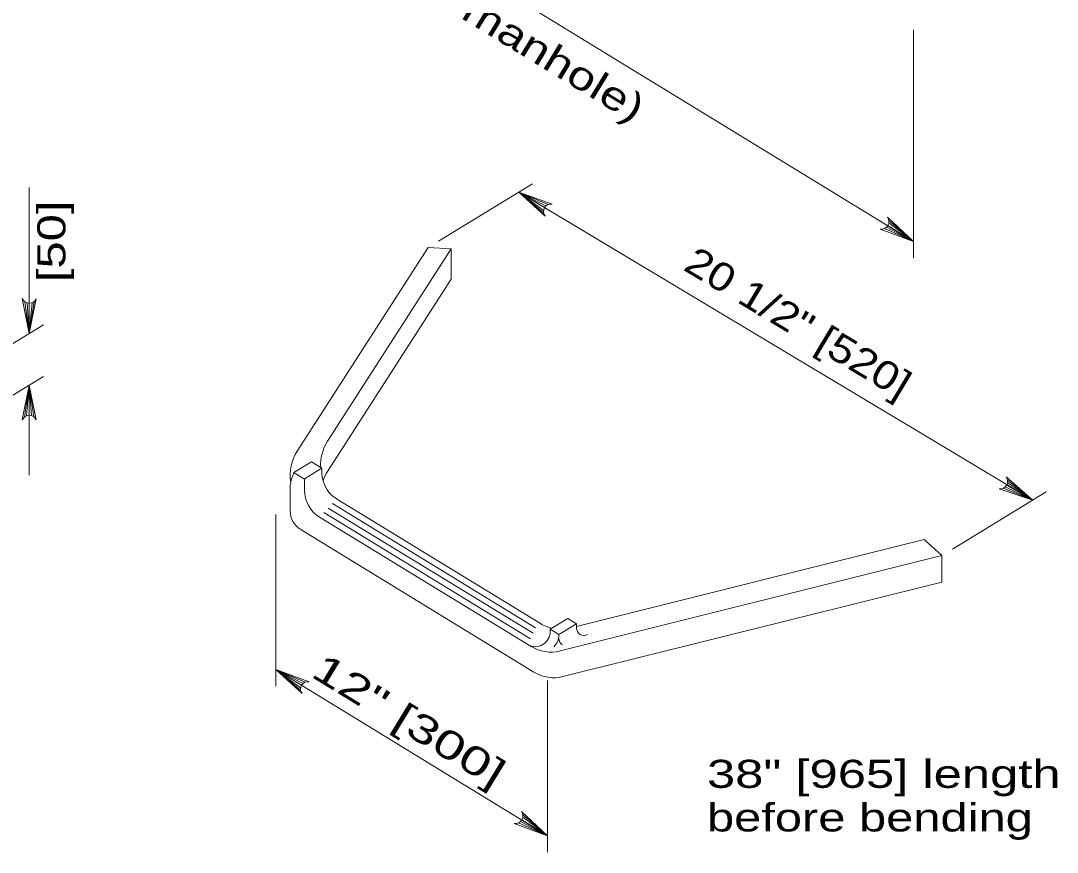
# Model space of a CAD drawing. Extents: x 1083.1 to 1117.1, y 697.4 to 741.4.
# Drawn here: x 1093.86 to 1099.62, y 705.78 to 710.4 of the extents above; entities that cross this region are included whole.
import ezdxf
from ezdxf.enums import TextEntityAlignment as Align

# ---------------------------------------------------------------- set-up
doc = ezdxf.new("R2010")
doc.units = 0
doc.header["$LTSCALE"] = 0.062
doc.layers.add('1', color=7, linetype='Continuous', lineweight=13)

msp = doc.modelspace()

# ---------------------------------------------------------------- linework, layer by layer
at = {"layer": '1'}
for p, q in [((1093.9525, 712.147), (1098.82075, 709.17125)), ((1098.82075, 709.07908), (1098.82075, 710.34608)), ((1093.91117, 709.47075), (1093.91117, 708.66008)), ((1096.1835, 709.17208), (1096.7045, 709.4905)), ((1096.77233, 709.35842), (1096.62867, 709.44417)), ((1096.76692, 709.34333), (1096.62867, 709.44417)), ((1096.76683, 709.33017), (1096.62867, 709.44417)), ((1096.78017, 709.36808), (1096.62867, 709.44417)), ((1096.7915, 709.3755), (1096.62867, 709.44417)), ((1096.62867, 709.44417), (1099.4825, 707.73375)), ((1098.684, 709.287), (1098.82075, 709.17125)), ((1098.65883, 709.242), (1098.82075, 709.17125)), ((1098.67017, 709.24925), (1098.82075, 709.17125)), ((1098.67825, 709.25883), (1098.82075, 709.17125)), ((1098.68383, 709.27383), (1098.82075, 709.17125)), ((1095.39808, 708.006), (1096.12508, 709.13633)), ((1095.56725, 708.06217), (1096.254, 709.12983)), ((1096.12508, 709.13633), (1096.254, 709.12983)), ((1096.254, 708.9615), (1096.254, 709.12983)), ((1095.56683, 707.89325), (1096.254, 708.9615)), ((1093.88667, 708.83508), (1093.91117, 708.66008)), ((1093.89875, 708.82917), (1093.91117, 708.66008)), ((1093.93817, 708.83717), (1093.91117, 708.66008)), ((1093.92683, 708.83042), (1093.91117, 708.66008)), ((1093.91117, 708.82733), (1093.91117, 708.66008)), ((1093.30033, 708.28675), (1093.98983, 708.70817)), ((1093.30033, 707.99925), (1093.98983, 708.42067)), ((1093.88408, 708.1955), (1093.91117, 708.37258)), ((1093.89542, 708.20225), (1093.91117, 708.37258)), ((1093.91117, 708.20533), (1093.91117, 708.37258)), ((1093.9235, 708.2035), (1093.91117, 708.37258)), ((1093.93558, 708.19758), (1093.91117, 708.37258)), ((1093.91117, 708.37258), (1093.91117, 707.872)), ((1095.37983, 707.88767), (1095.47742, 707.94733)), ((1095.43875, 707.85167), (1095.53633, 707.91133)), ((1095.53633, 707.91133), (1095.47742, 707.94733)), ((1095.37983, 707.88767), (1095.36592, 707.84433)), ((1095.43975, 707.85108), (1095.37983, 707.88767)), ((1095.43975, 707.79108), (1095.43975, 707.85108)), ((1099.34275, 707.84575), (1099.4825, 707.73375)), ((1095.36, 707.67392), (1095.36, 707.8065)), ((1099.31875, 707.80008), (1099.4825, 707.73375)), ((1099.32992, 707.80758), (1099.4825, 707.73375)), ((1099.33767, 707.81742), (1099.4825, 707.73375)), ((1099.34283, 707.83258), (1099.4825, 707.73375)), ((1096.75033, 707.04883), (1095.61708, 707.74142)), ((1099.03733, 707.46167), (1099.55825, 707.78008)), ((1096.70825, 706.99467), (1095.57, 707.69042)), ((1096.72242, 707.02592), (1095.59392, 707.71575)), ((1095.2805, 706.70092), (1095.2805, 707.65492)), ((1096.697, 706.92175), (1095.52208, 707.63992)), ((1096.69417, 706.96342), (1095.54617, 707.66508)), ((1096.713, 706.77933), (1095.41458, 707.573)), ((1096.94917, 707.03308), (1098.88083, 707.51525)), ((1098.97892, 707.42592), (1098.88083, 707.51525)), ((1096.85825, 706.89667), (1098.97892, 707.42592)), ((1098.97892, 707.2795), (1098.97892, 707.42592)), ((1096.8735, 706.754), (1098.97892, 707.2795)), ((1096.80367, 707.01742), (1096.90125, 707.077)), ((1096.85167, 706.98808), (1096.94917, 707.04767)), ((1096.94917, 707.04767), (1096.90125, 707.077)), ((1096.94917, 707.02583), (1096.94917, 707.04767)), ((1096.85167, 706.98808), (1096.80367, 707.01742)), ((1096.80367, 707.00775), (1096.80367, 707.01742)), ((1095.42358, 706.70642), (1095.2805, 706.79308)), ((1095.418, 706.69142), (1095.2805, 706.79308)), ((1095.41792, 706.67825), (1095.2805, 706.79308)), ((1095.4315, 706.71608), (1095.2805, 706.79308)), ((1095.44283, 706.72333), (1095.2805, 706.79308)), ((1096.78892, 705.87108), (1095.2805, 706.79308)), ((1096.78892, 705.77892), (1096.78892, 706.73292)), ((1096.63833, 705.94892), (1096.78892, 705.87108)), ((1096.64633, 705.95858), (1096.78892, 705.87108)), ((1096.65192, 705.97358), (1096.78892, 705.87108)), ((1096.65208, 705.98675), (1096.78892, 705.87108)), ((1096.62692, 705.94175), (1096.78892, 705.87108))]:
    msp.add_line(p, q, dxfattribs=at)
for points in [[(1096.77483, 709.31192), (1096.62867, 709.44417), (1096.8145, 709.37825)], [(1098.67625, 709.30533), (1098.82075, 709.17125), (1098.63583, 709.2395)], [(1093.94983, 708.85342), (1093.91117, 708.66008), (1093.8725, 708.85342)], [(1093.8725, 708.17925), (1093.91117, 708.37258), (1093.94983, 708.17925)], [(1099.33442, 707.86392), (1099.4825, 707.73375), (1099.29583, 707.79692)], [(1095.42575, 706.65983), (1095.2805, 706.79308), (1095.46583, 706.726)], [(1096.64433, 706.00508), (1096.78892, 705.87108), (1096.60392, 705.93917)]]:
    msp.add_lwpolyline(points, dxfattribs=at)
for centre, start, end in [((1096.80807, 709.33712), 81.24479, 217.07092), ((1098.64271, 709.28055), 260.53947, 36.3656), ((1093.91109, 708.86899), 202.08782, 337.91395), ((1093.91118, 708.16367), 22.08782, 157.91395), ((1099.30159, 707.8382), 262.08782, 37.91395), ((1095.45917, 706.68488), 80.86737, 216.6935), ((1096.61079, 705.98028), 260.56849, 36.39462)]:
    msp.add_arc(centre, 0.04172, start, end, dxfattribs=at)
for centre, major_axis, start_param, end_param in [((1095.74994, 707.93046), (0, 0.234), 0.9729753, 1.634587), ((1095.58073, 707.87426), (0, 0.234), 0.9729767, 1.739803), ((1095.70027, 707.89226), (0, -0.17462), 4.6113087, 5.7636801), ((1095.47049, 707.80655), (0, 0.117), 1.2421403, 1.5709153), ((1095.74994, 707.76214), (0, 0.234), 0.9729753, 1.2216373), ((1095.60473, 707.79104), (0, -0.17462), 4.7123887, 5.7595856), ((1095.47047, 707.67389), (0, -0.117), 4.712389, 5.765441), ((1096.86082, 707.25144), (0, -0.234), 5.7595872, 6.0646631), ((1096.72122, 707.00776), (0, -0.08731), 5.7595855, 7.8539813), ((1096.7692, 706.98605), (0, -0.08731), 0.7214123, 1.5707936), ((1096.99044, 707.02585), (0, 0.04366), 1.5707898, 3.6651902), ((1096.8929, 706.96623), (0, 0.04366), 1.5707936, 2.5275854), ((1096.80754, 707.12438), (0, -0.234), 5.7595853, 6.5147206), ((1096.82349, 706.98195), (0, -0.234), 5.7595865, 6.5147204)]:
    msp.add_ellipse(centre, major_axis=major_axis, ratio=0.944544, start_param=start_param, end_param=end_param, dxfattribs=at)

# ---------------------------------------------------------------- texts
for s, rotation, width, p in [('(for 48" [1200] dia. manhole)', 328.565, 1.3, (1094.34083, 711.613)), ('20 1/2" [520]', 329.064, 1.2, (1097.53517, 709.01608)), ('12" [300]', 328.565, 1.45, (1095.46725, 706.75842))]:
    msp.add_text(s, height=0.156, rotation=rotation, dxfattribs=dict(at, width=width)).set_placement(p)
at = {"layer": '1', "width": 1.3}
msp.add_text('[50]', height=0.156, rotation=90, dxfattribs=at).set_placement((1094.11192, 709.17129), align=Align.CENTER)
at = {"layer": '1'}
for s, width, p in [('38" [965] length', 1.35, (1097.67392, 706.13642)), ('before bending', 1.3, (1097.67392, 705.8945))]:
    msp.add_text(s, height=0.156, dxfattribs=dict(at, width=width)).set_placement(p)

doc.saveas('drawing.dxf')
